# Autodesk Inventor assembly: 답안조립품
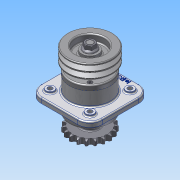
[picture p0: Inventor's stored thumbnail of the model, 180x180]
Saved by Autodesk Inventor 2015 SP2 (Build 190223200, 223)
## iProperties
Created: 2015-07
Part Number: 답안조립품
Document SubType Name: Assembly
Designer: AMC
Author: AMC
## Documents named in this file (12)
- C:\Users\AMC\Desktop\450735V1002\답안조립품.iam
- C:\Users\AMC\Desktop\450735V1002\본체.ipt
- C:\Users\AMC\Desktop\450735V1002\2-커버.ipt
- C:\Users\AMC\Desktop\450735V1002\3-축.ipt
- C:\Users\AMC\Desktop\450735V1002\4-V벨트풀리.ipt
- C:\Users\AMC\Desktop\450735V1002\5-체인 스프로킷.ipt
- C:\Users\AMC\Desktop\450735V1002\6-베어링 6206.ipt
- C:\Users\AMC\Desktop\450735V1002\7-부시.ipt
- C:\Users\AMC\Desktop\450735V1002\8-오일실 30x42.ipt
- C:\Users\AMC\Desktop\450735V1002\9-M16-너트.ipt
- C:\Users\AMC\Desktop\450735V1002\10-M6.ipt
- C:\Users\AMC\Desktop\450735V1002\11-키 6x6.ipt
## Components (22 placed, 10 different names)
1. 2-커버:1
2. 3-축:1
3. 4-V벨트풀리:1 — 각도:1
4. 5-체인 스프로킷:1 — 각도:2
5. 6-베어링 6206:1
6. 7-부시:1
7. 8-8-오일실 30x42:1
8. 9-M16 너트:1
9. 10-M6:1
10. 11-키 6x6:1 — 각도:1
11. 6-베어링 6206:2
12. 2-커버:2
13. 8-8-오일실 30x42:2
14. 11-키 6x6:2 — 각도:2
15. 10-M6:2
16. 10-M6:3
17. 10-M6:4
18. 10-M6:5
19. 10-M6:6
20. 10-M6:7
21. 10-M6:8
22. 9-M16 너트:2
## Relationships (2: Angle 2)
- 각도:1 [Angle]: 4-V벨트풀리:1 ↔ 11-키 6x6:1
- 각도:2 [Angle]: 5-체인 스프로킷:1 ↔ 11-키 6x6:2
